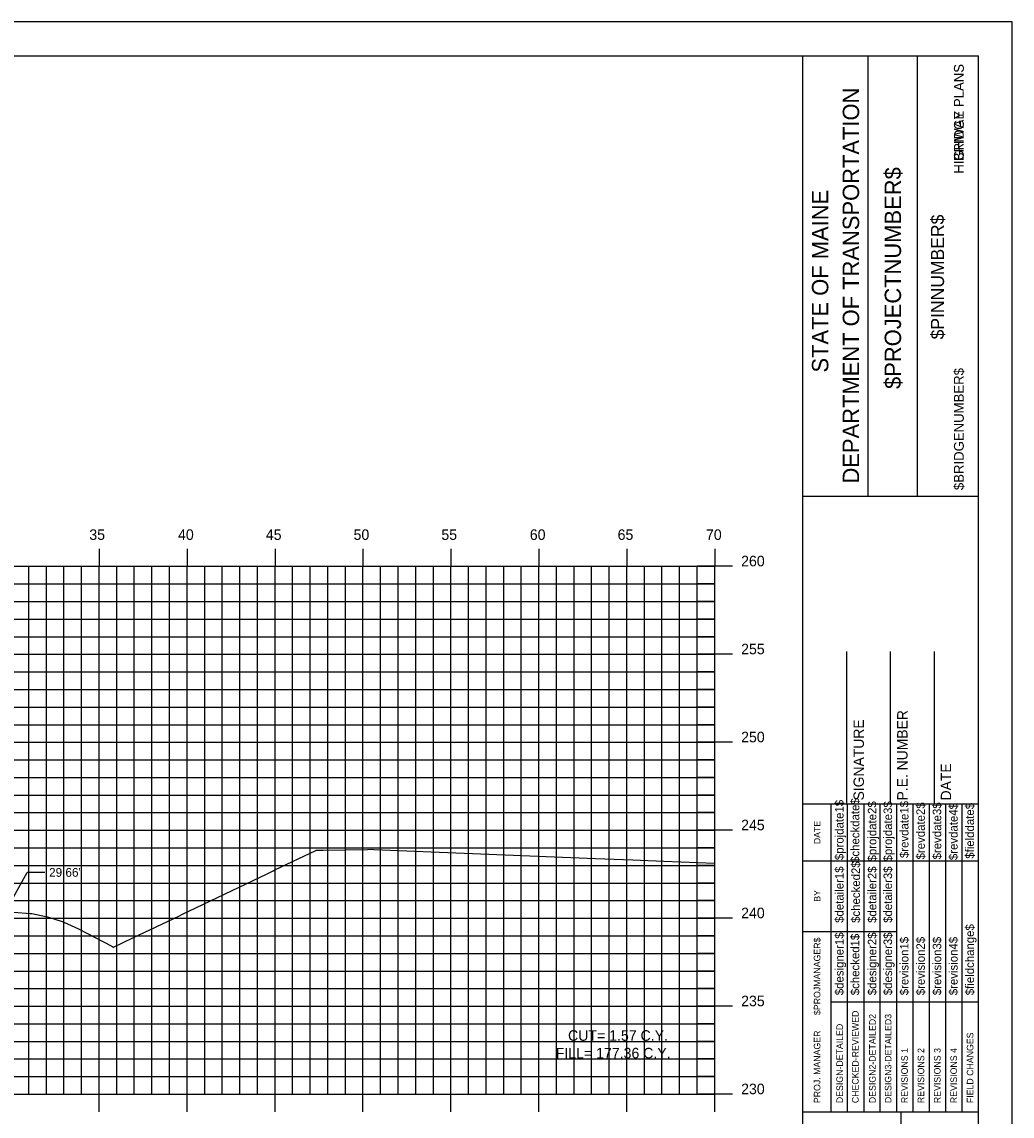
# Model space of a CAD drawing. Extents: x 1170543 to 1177585, y 609599 to 610623.
# Drawn here: x 1172726.6 to 1172782.9, y 609646.6 to 609708.8 of the extents above; entities that cross this region are included whole.
import ezdxf

# ---------------------------------------------------------------- set-up
doc = ezdxf.new("R2010")
doc.units = 0
for name, color, linetype in [('ANNOTATION', 7, 'Continuous'), ('BORDER', 7, 'Continuous'), ('BRIDGE_TITLE', 7, 'Continuous'), ('D_Roadway_Centerline_Text', 7, 'Continuous'), ('H_V ANNOTATION', 7, 'Continuous'), ('HIGHWAY_TITLE', 7, 'Continuous'), ('MAJOR', 7, 'Continuous'), ('MINOR', 7, 'Continuous'), ('PLOT BOUNDARY', 7, 'Continuous'), ('S_Roadway_Centerline', 7, 'Continuous')]:
    doc.layers.add(name, color=color, linetype=linetype)

msp = doc.modelspace()

# ---------------------------------------------------------------- linework, layer by layer
at = {"layer": 'ANNOTATION'}
for p in [(1172725.655, 609658.226), (1172727.894, 609660.478)]:
    msp.add_line(p, (1172726.894, 609660.478), dxfattribs=at)
at = {"layer": 'BORDER'}
for p, q in [((1172780.991, 609706.872), (1172620.991, 609706.872)), ((1172770.991, 609601.875), (1172770.991, 609706.875)), ((1172774.72, 609681.869), (1172774.72, 609706.869)), ((1172777.515, 609681.869), (1172777.515, 609706.869)), ((1172780.991, 609601.875), (1172780.991, 609706.875)), ((1172770.992, 609681.866), (1172780.991, 609681.866)), ((1172773.491, 609664.375), (1172773.491, 609673.023)), ((1172775.991, 609664.375), (1172775.991, 609673.023)), ((1172778.491, 609664.375), (1172778.491, 609673.023)), ((1172770.991, 609664.375), (1172780.991, 609664.375)), ((1172770.991, 609646.875), (1172780.991, 609646.875)), ((1172776.582, 609611.875), (1172776.582, 609646.875))]:
    msp.add_line(p, q, dxfattribs=at)
for points in [[(1172772.606, 609661.125), (1172772.606, 609664.375)], [(1172773.539, 609646.878), (1172773.539, 609664.375)], [(1172774.47, 609664.375), (1172774.47, 609646.878)], [(1172775.402, 609646.878), (1172775.402, 609664.375)], [(1172776.334, 609646.878), (1172776.334, 609664.375)], [(1172777.265, 609646.878), (1172777.265, 609664.375)], [(1172778.197, 609646.878), (1172778.197, 609664.375)], [(1172779.129, 609646.878), (1172779.129, 609664.375)], [(1172780.06, 609646.878), (1172780.06, 609664.375)], [(1172772.607, 609646.878), (1172772.607, 609663.669)], [(1172770.991, 609661.125), (1172780.991, 609661.125)], [(1172770.991, 609657.125), (1172772.607, 609657.125)], [(1172772.606, 609657.125), (1172776.333, 609657.125)], [(1172772.606, 609653.125), (1172780.991, 609653.125)]]:
    msp.add_lwpolyline(points, dxfattribs=at)
at = {"layer": 'MAJOR'}
for p, q in [((1172730.991, 609678.874), (1172730.991, 609677.872)), ((1172735.991, 609678.874), (1172735.991, 609677.872)), ((1172740.991, 609678.874), (1172740.991, 609677.872)), ((1172745.991, 609678.874), (1172745.991, 609677.872)), ((1172750.991, 609678.874), (1172750.991, 609677.872)), ((1172755.991, 609678.874), (1172755.991, 609677.872)), ((1172760.991, 609678.874), (1172760.991, 609677.872)), ((1172765.991, 609678.874), (1172765.991, 609677.872)), ((1172625.991, 609677.872), (1172765.991, 609677.872)), ((1172625.991, 609677.872), (1172765.991, 609677.872)), ((1172730.991, 609647.872), (1172730.991, 609677.872)), ((1172735.991, 609647.872), (1172735.991, 609677.872)), ((1172740.991, 609647.872), (1172740.991, 609677.872)), ((1172745.991, 609647.872), (1172745.991, 609677.872)), ((1172750.991, 609647.872), (1172750.991, 609677.872)), ((1172755.991, 609647.872), (1172755.991, 609677.872)), ((1172760.991, 609647.872), (1172760.991, 609677.872)), ((1172766.993, 609677.872), (1172764.989, 609677.872)), ((1172765.991, 609647.872), (1172765.991, 609677.872)), ((1172765.991, 609647.872), (1172765.991, 609677.872)), ((1172625.991, 609672.872), (1172765.991, 609672.872)), ((1172766.993, 609672.872), (1172764.989, 609672.872)), ((1172625.991, 609667.872), (1172765.991, 609667.872)), ((1172766.993, 609667.872), (1172764.989, 609667.872)), ((1172625.991, 609662.872), (1172765.991, 609662.872)), ((1172766.993, 609662.872), (1172764.989, 609662.872)), ((1172625.991, 609657.872), (1172765.991, 609657.872)), ((1172766.993, 609657.872), (1172764.989, 609657.872)), ((1172625.991, 609652.872), (1172765.991, 609652.872)), ((1172766.993, 609652.872), (1172764.989, 609652.872)), ((1172625.991, 609647.872), (1172765.991, 609647.872)), ((1172625.991, 609647.872), (1172765.991, 609647.872)), ((1172730.991, 609646.87), (1172730.991, 609647.872)), ((1172735.991, 609646.87), (1172735.991, 609647.872)), ((1172740.991, 609646.87), (1172740.991, 609647.872)), ((1172745.991, 609646.87), (1172745.991, 609647.872)), ((1172750.991, 609646.87), (1172750.991, 609647.872)), ((1172755.991, 609646.87), (1172755.991, 609647.872)), ((1172760.991, 609646.87), (1172760.991, 609647.872)), ((1172766.993, 609647.872), (1172764.989, 609647.872)), ((1172765.991, 609646.87), (1172765.991, 609647.872))]:
    msp.add_line(p, q, dxfattribs=at)
at = {"layer": 'MINOR'}
for p, q in [((1172726.991, 609647.872), (1172726.991, 609677.872)), ((1172727.991, 609647.872), (1172727.991, 609677.872)), ((1172728.991, 609647.872), (1172728.991, 609677.872)), ((1172729.991, 609647.872), (1172729.991, 609677.872)), ((1172731.991, 609647.872), (1172731.991, 609677.872)), ((1172732.991, 609647.872), (1172732.991, 609677.872)), ((1172733.991, 609647.872), (1172733.991, 609677.872)), ((1172734.991, 609647.872), (1172734.991, 609677.872)), ((1172736.991, 609647.872), (1172736.991, 609677.872)), ((1172737.991, 609647.872), (1172737.991, 609677.872)), ((1172738.991, 609647.872), (1172738.991, 609677.872)), ((1172739.991, 609647.872), (1172739.991, 609677.872)), ((1172741.991, 609647.872), (1172741.991, 609677.872)), ((1172742.991, 609647.872), (1172742.991, 609677.872)), ((1172743.991, 609647.872), (1172743.991, 609677.872)), ((1172744.991, 609647.872), (1172744.991, 609677.872)), ((1172746.991, 609647.872), (1172746.991, 609677.872)), ((1172747.991, 609647.872), (1172747.991, 609677.872)), ((1172748.991, 609647.872), (1172748.991, 609677.872)), ((1172749.991, 609647.872), (1172749.991, 609677.872)), ((1172751.991, 609647.872), (1172751.991, 609677.872)), ((1172752.991, 609647.872), (1172752.991, 609677.872)), ((1172753.991, 609647.872), (1172753.991, 609677.872)), ((1172754.991, 609647.872), (1172754.991, 609677.872)), ((1172756.991, 609647.872), (1172756.991, 609677.872)), ((1172757.991, 609647.872), (1172757.991, 609677.872)), ((1172758.991, 609647.872), (1172758.991, 609677.872)), ((1172759.991, 609647.872), (1172759.991, 609677.872)), ((1172761.991, 609647.872), (1172761.991, 609677.872)), ((1172762.991, 609647.872), (1172762.991, 609677.872)), ((1172763.991, 609647.872), (1172763.991, 609677.872)), ((1172764.991, 609647.872), (1172764.991, 609677.872)), ((1172625.991, 609676.872), (1172765.991, 609676.872)), ((1172765.991, 609676.872), (1172764.989, 609676.872)), ((1172625.991, 609675.872), (1172765.991, 609675.872)), ((1172765.991, 609675.872), (1172764.989, 609675.872)), ((1172625.991, 609674.872), (1172765.991, 609674.872)), ((1172765.991, 609674.872), (1172764.989, 609674.872)), ((1172625.991, 609673.872), (1172765.991, 609673.872)), ((1172765.991, 609673.872), (1172764.989, 609673.872)), ((1172625.991, 609671.872), (1172765.991, 609671.872)), ((1172765.991, 609671.872), (1172764.989, 609671.872)), ((1172625.991, 609670.872), (1172765.991, 609670.872)), ((1172765.991, 609670.872), (1172764.989, 609670.872)), ((1172625.991, 609669.872), (1172765.991, 609669.872)), ((1172765.991, 609669.872), (1172764.989, 609669.872)), ((1172625.991, 609668.872), (1172765.991, 609668.872)), ((1172765.991, 609668.872), (1172764.989, 609668.872)), ((1172625.991, 609666.872), (1172765.991, 609666.872)), ((1172765.991, 609666.872), (1172764.989, 609666.872)), ((1172625.991, 609665.872), (1172765.991, 609665.872)), ((1172765.991, 609665.872), (1172764.989, 609665.872)), ((1172625.991, 609664.872), (1172765.991, 609664.872)), ((1172765.991, 609664.872), (1172764.989, 609664.872)), ((1172625.991, 609663.872), (1172765.991, 609663.872)), ((1172765.991, 609663.872), (1172764.989, 609663.872)), ((1172625.991, 609661.872), (1172765.991, 609661.872)), ((1172765.991, 609661.872), (1172764.989, 609661.872)), ((1172625.991, 609660.872), (1172765.991, 609660.872)), ((1172765.991, 609660.872), (1172764.989, 609660.872)), ((1172625.991, 609659.872), (1172765.991, 609659.872)), ((1172765.991, 609659.872), (1172764.989, 609659.872)), ((1172625.991, 609658.872), (1172765.991, 609658.872)), ((1172765.991, 609658.872), (1172764.989, 609658.872)), ((1172625.991, 609656.872), (1172765.991, 609656.872)), ((1172765.991, 609656.872), (1172764.989, 609656.872)), ((1172625.991, 609655.872), (1172765.991, 609655.872)), ((1172765.991, 609655.872), (1172764.989, 609655.872)), ((1172625.991, 609654.872), (1172765.991, 609654.872)), ((1172765.991, 609654.872), (1172764.989, 609654.872)), ((1172625.991, 609653.872), (1172765.991, 609653.872)), ((1172765.991, 609653.872), (1172764.989, 609653.872)), ((1172625.991, 609651.872), (1172765.991, 609651.872)), ((1172765.991, 609651.872), (1172764.989, 609651.872)), ((1172625.991, 609650.872), (1172765.991, 609650.872)), ((1172765.991, 609650.872), (1172764.989, 609650.872)), ((1172625.991, 609649.872), (1172765.991, 609649.872)), ((1172765.991, 609649.872), (1172764.989, 609649.872)), ((1172625.991, 609648.872), (1172765.991, 609648.872)), ((1172765.991, 609648.872), (1172764.989, 609648.872))]:
    msp.add_line(p, q, dxfattribs=at)
at = {"layer": 'PLOT BOUNDARY'}
msp.add_lwpolyline([(1172612.898, 609598.813), (1172782.898, 609598.813), (1172782.898, 609708.813), (1172612.898, 609708.813)], close=True, dxfattribs=at)
at = {"layer": 'S_Roadway_Centerline'}
msp.add_lwpolyline([(1172726.149, 609658.212), (1172727.071, 609658.145), (1172727.162, 609658.136), (1172727.968, 609657.973), (1172728.062, 609657.953), (1172728.883, 609657.681), (1172728.977, 609657.648), (1172729.814, 609657.265), (1172731.706, 609656.276), (1172731.807, 609656.23), (1172732.904, 609656.749), (1172735.552, 609658.017), (1172735.553, 609658.016), (1172735.554, 609658.016), (1172735.685, 609658.079), (1172740.539, 609660.402), (1172740.876, 609660.563), (1172740.988, 609660.616), (1172743.304, 609661.725), (1172743.325, 609661.734), (1172743.348, 609661.735), (1172743.721, 609661.741), (1172746.246, 609661.785), (1172746.448, 609661.789), (1172746.609, 609661.782), (1172759.218, 609661.274), (1172761.331, 609661.189), (1172763.103, 609661.117), (1172765.991, 609661.001)], dxfattribs=at)

# ---------------------------------------------------------------- texts
at = {"layer": 'ANNOTATION'}
msp.add_text("29.66'", height=0.5, dxfattribs=at).set_placement((1172728.144, 609660.228))
at = {"layer": 'BORDER'}
for s, height, p in [('DEPARTMENT OF TRANSPORTATION', 0.93176, (1172774.198, 609682.578)), ('$PROJECTNUMBER$', 0.93176, (1172776.583, 609687.951)), ('STATE OF MAINE', 0.93176, (1172772.447, 609688.884)), ('$PINNUMBER$', 0.74527, (1172779.028, 609690.769)), ('P.E. NUMBER', 0.59055, (1172776.952, 609664.567)), ('SIGNATURE', 0.5906, (1172774.472, 609664.567)), ('DATE', 0.5906, (1172779.432, 609664.567)), ('$checkdate$', 0.48455, (1172774.209, 609661.018)), ('$projdate1$', 0.48455, (1172773.314, 609661.176)), ('$projdate2$', 0.48455, (1172775.178, 609661.097)), ('$projdate3$', 0.48455, (1172776.072, 609661.097)), ('$revdate1$', 0.4845, (1172777.004, 609661.294)), ('$revdate2$', 0.4845, (1172777.935, 609661.215)), ('$revdate3$', 0.4845, (1172778.867, 609661.215)), ('$revdate4$', 0.4845, (1172779.799, 609661.176)), ('$fielddate$', 0.48455, (1172780.73, 609661.254)), ('DATE', 0.3714, (1172771.996, 609662.081)), ('$checked2$', 0.4845, (1172774.246, 609657.61)), ('$detailer1$', 0.48455, (1172773.314, 609657.61)), ('$detailer2$', 0.48455, (1172775.178, 609657.61)), ('$detailer3$', 0.48455, (1172776.072, 609657.61)), ('BY', 0.3714, (1172771.996, 609658.81)), ('$fieldchange$', 0.48455, (1172780.73, 609653.498)), ('$PROJMANAGER$', 0.37275, (1172771.996, 609652.37)), ('$designer1$', 0.48455, (1172773.314, 609653.498)), ('$checked1$', 0.4845, (1172774.209, 609653.498)), ('$designer2$', 0.48455, (1172775.178, 609653.498)), ('$designer3$', 0.48455, (1172776.072, 609653.498)), ('$revision1$', 0.48455, (1172777.004, 609653.498)), ('$revision2$', 0.48455, (1172777.935, 609653.498)), ('$revision3$', 0.48455, (1172778.867, 609653.498)), ('$revision4$', 0.48455, (1172779.799, 609653.498)), ('CHECKED-REVIEWED', 0.37275, (1172774.172, 609647.363)), ('DESIGN2-DETAILED2', 0.37275, (1172775.141, 609647.363)), ('DESIGN3-DETAILED3', 0.37275, (1172776.036, 609647.363)), ('DESIGN-DETAILED', 0.37275, (1172773.278, 609647.363)), ('PROJ. MANAGER', 0.37275, (1172771.996, 609647.363)), ('FIELD CHANGES', 0.37275, (1172780.694, 609647.363)), ('REVISIONS 1', 0.37275, (1172776.967, 609647.363)), ('REVISIONS 2', 0.37275, (1172777.899, 609647.363)), ('REVISIONS 3', 0.37275, (1172778.831, 609647.363)), ('REVISIONS 4', 0.37275, (1172779.762, 609647.363))]:
    msp.add_text(s, height=height, rotation=90, dxfattribs=at).set_placement(p)
at = {"layer": 'BRIDGE_TITLE'}
for s, p in [('BRIDGE PLANS', (1172780.15, 609700.897)), ('$BRIDGENUMBER$', (1172780.15, 609682.203))]:
    msp.add_text(s, height=0.55901, rotation=90, dxfattribs=at).set_placement(p)
at = {"layer": 'D_Roadway_Centerline_Text'}
for s, p in [('CUT= 1.57 C.Y.', (1172757.649, 609650.908)), ('FILL= 177.36 C.Y.', (1172756.949, 609649.906))]:
    msp.add_text(s, height=0.6, dxfattribs=at).set_placement(p)
at = {"layer": 'H_V ANNOTATION'}
for s, p in [('35', (1172730.432, 609679.372)), ('40', (1172735.477, 609679.372)), ('45', (1172740.469, 609679.372)), ('50', (1172745.456, 609679.372)), ('55', (1172750.448, 609679.372)), ('60', (1172755.477, 609679.372)), ('65', (1172760.469, 609679.372)), ('70', (1172765.493, 609679.372)), ('260', (1172767.491, 609677.872)), ('255', (1172767.491, 609672.872)), ('250', (1172767.491, 609667.872)), ('245', (1172767.491, 609662.872)), ('240', (1172767.491, 609657.872)), ('235', (1172767.491, 609652.872)), ('230', (1172767.491, 609647.872))]:
    msp.add_text(s, height=0.6, dxfattribs=at).set_placement(p)
at = {"layer": 'HIGHWAY_TITLE'}
msp.add_text('HIGHWAY PLANS', height=0.55901, rotation=90, dxfattribs=at).set_placement((1172780.15, 609700.188))

doc.saveas('drawing.dxf')
